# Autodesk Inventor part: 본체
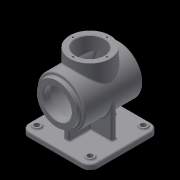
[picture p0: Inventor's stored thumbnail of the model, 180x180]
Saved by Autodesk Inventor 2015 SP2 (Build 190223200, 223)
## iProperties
Created: 2015-07
Part Number: 본체
Material: 알루미늄 6061
Document SubType Name: Modeling
Designer: AMC
Density: 2.7 g/cm^3
Appearance: 기본값
Mass: 1272.91 g
Surface Area: 1267.64 cm^2
Volume: 471.446 cm^3
Author: AMC
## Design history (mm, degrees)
sketch "스케치1"
  geometry: L1 (65, -65)-(-65, -65); L2 (-65, -65)-(-65, 65); L3 (-65, 65)-(65, 65); L4 (65, 65)-(65, -65); L5 (65, -65)-(-65, 65); L6 (-65, -65)-(65, 65); 1 further point
  constraints: 12 end point, 2 midpoint, 2 parallel, 2 perpendicular, 1 horizontal
  dimensions: "d0" = 130 distance of L1.end L2.end
extrude "돌출1" new body sketch "스케치1" distance "d1" = 10; taper "d2" = 0 deg
sketch "스케치2"
  geometry: C1 r 45 at (0, 78); 1 further point
  constraints: 1 centre point, 1 vertical alignment
  dimensions: "d3" = 78 distance of point (0, 0) C1.centre; "d4" = 90 diameter of C1
extrude "돌출2" join sketch "스케치2" stored distance "d5" = 110; taper "d6" = 0 deg
sketch "스케치3"
  geometry: C1 r 45 at (0, 0) reference; C2 r 38 at (0, 0); 1 further point
  constraints: 1 centre point, 1 coincident
  dimensions: "d7" = 76 diameter of C2
extrude "돌출3" join sketch "스케치3" distance "d8" = 7; taper "d9" = 0 deg
node "작업 평면1"
sketch "스케치4"
  geometry: C1 r 38 at (0, 0); 1 further point
  constraints: 1 centre point, 1 coincident
  dimensions: "d11" = 76 diameter of C1
extrude "돌출4" join sketch "스케치4" stored distance "d12" = 7; taper "d13" = 0 deg
sketch "스케치5"
  geometry: L1 (-62, 116)-(-62, 40) reference; L2 (55, 33)-(55, 123) reference; L3 (-62, 78)-(55, 78); L4 (-62, 105)-(-48, 105); L5 (-48, 105)-(-48, 115); L6 (-45, 118)-(45, 118); L7 (48, 115)-(48, 78); A1 r 3 centre (-45, 115) between (-45, 118) and (-48, 115); A2 r 3 centre (45, 115) between (48, 115) and (45, 118); 1 further point
  constraints: 10 end point, 4 point on circle, 4 tangent, 3 perpendicular, 2 centre point, 2 midpoint, 2 point on line, 1 horizontal
  dimensions: "d14" = 14 distance between parallel lines of L5 L1; "d15" = 96 distance between parallel lines of L7 L5; "d16" = 54 diameter of L4 L3; "d17" = 80 diameter of L6 L3; "d18" = 3 radius of A1; "d19" = 3 radius of A2
revolve "회전1" sketch "스케치5" stored, may be unused: angle "d20" = 90 deg
hole "구멍1" diameter "d23" = 54; stored, may be unused: countersink angle "d27" = 90 deg, drill point angle "d29" = 118 deg; dims "d21" = 10, "d22" = 10, "d24" = 6, "d25" = 54, "d26" = 14, "d28" = 8
sketch "스케치6"
  geometry: 2 further points
  constraints: 1 horizontal alignment
  dimensions: "d30" = 32 distance of point (0, 0) point (-32, 0)
hole "구멍2" sketch "스케치6" at (-32, 0) diameter "d31" = 3.242; stored, may be unused: countersink angle "d35" = 90 deg, drill point angle "d37" = 118 deg; dims "d32" = 8, "d33" = 54, "d34" = 14, "d36" = 10
sketch "스케치7"
  geometry: C1 r 27 at (0, 0) reference; 2 further points
  constraints: 1 vertical alignment
  dimensions: "d41" = 32 distance of C1.centre point (0, 32)
hole "구멍3" sketch "스케치7" at (0, 32) diameter "d42" = 3.242; stored, may be unused: countersink angle "d46" = 90 deg, drill point angle "d48" = 118 deg; dims "d43" = 8, "d44" = 54, "d45" = 14, "d47" = 10
sketch "스케치8"
  geometry: L1 (65, 0)-(-65, 0) reference; L2 (65, 0)-(65, 10) reference; L3 (-65, 10)-(65, 10) reference; L4 (-65, 0)-(-65, 10) reference; L5 (45, 78)-(45, 10); L6 (-65, 10)-(65, 10) reference; L7 (-45, 78)-(-45, 10); A1 r 45 centre (0, 78) between (45, 78) and (-45, 78) reference; 1 further point
  constraints: 4 end point, 2 point on circle, 2 point on line, 2 tangent, 1 parallel, 1 perpendicular, 1 vertical
extrude "돌출5" join sketch "스케치8" stored distance "d52" = 10; taper "d53" = 0 deg
sketch "스케치9"
  geometry: L1 (-55, 33)-(55, 33) reference; L2 (65, 10)-(-65, 10) reference; L3 (-45, 10)-(-45, 33); 1 further point
  constraints: 2 end point, 2 point on line, 1 perpendicular
  dimensions: "d54" = 45 distance from line of point (0, 0) L3
feature "리브1" sketch "스케치9" dims "d55" = 1, "d56" = 10, "d57" = 0, "d58" = 0, "d59" = 1, "d60" = 1
fillet "모깎기1" dims "d61" = 15
sketch "스케치10"
  geometry: C1 r 7.5 at (50, -50); 1 further point
  constraints: 1 centre point
  dimensions: "d62" = 15 diameter of C1; "d63" = 50 horizontal distance of point (0, 0) C1.centre; "d64" = 50 horizontal distance of point (0, 0) C1.centre
extrude "돌출6" join sketch "스케치10" distance "d65" = 3; taper "d66" = 0 deg
sketch "스케치11"
  geometry: C1 r 7.5 at (0, 0) reference; C2 r 5 at (0, 0); 1 further point
  constraints: 1 centre point, 1 coincident
  dimensions: "d67" = 10 diameter of C2
extrude "돌출7" cut sketch "스케치11" stored distance "d68" = 3; taper "d69" = 0 deg
fillet "모깎기2" dims "d70" = 3
fillet "모깎기3" dims "d77" = 3
fillet "모깎기4" dims "d78" = 3
chamfer "모따기1" distance "d79" = 1; stored, may be unused: second distance "d80" = 2, angle "d81" = 45 deg
sketch "스케치12"
  geometry: C1 r 42 at (0, 0) reference; 2 further points
  constraints: 2 coincident, 1 other
feature "엠보싱1" sketch "스케치12" dims "d0" = 130, "d11" = 76, "d82" = 0.5, "d83" = 0
node "솔리드1"
pattern_circular "원형 패턴1" dims angle "d39" = 360 deg
pattern_circular "원형 패턴2" dims angle "d50" = 360 deg
mirror "대칭1"
pattern_linear "직사각형 패턴1"
node "투영된 루프1"
node "투영된 루프2"
node "투영된 루프3"
